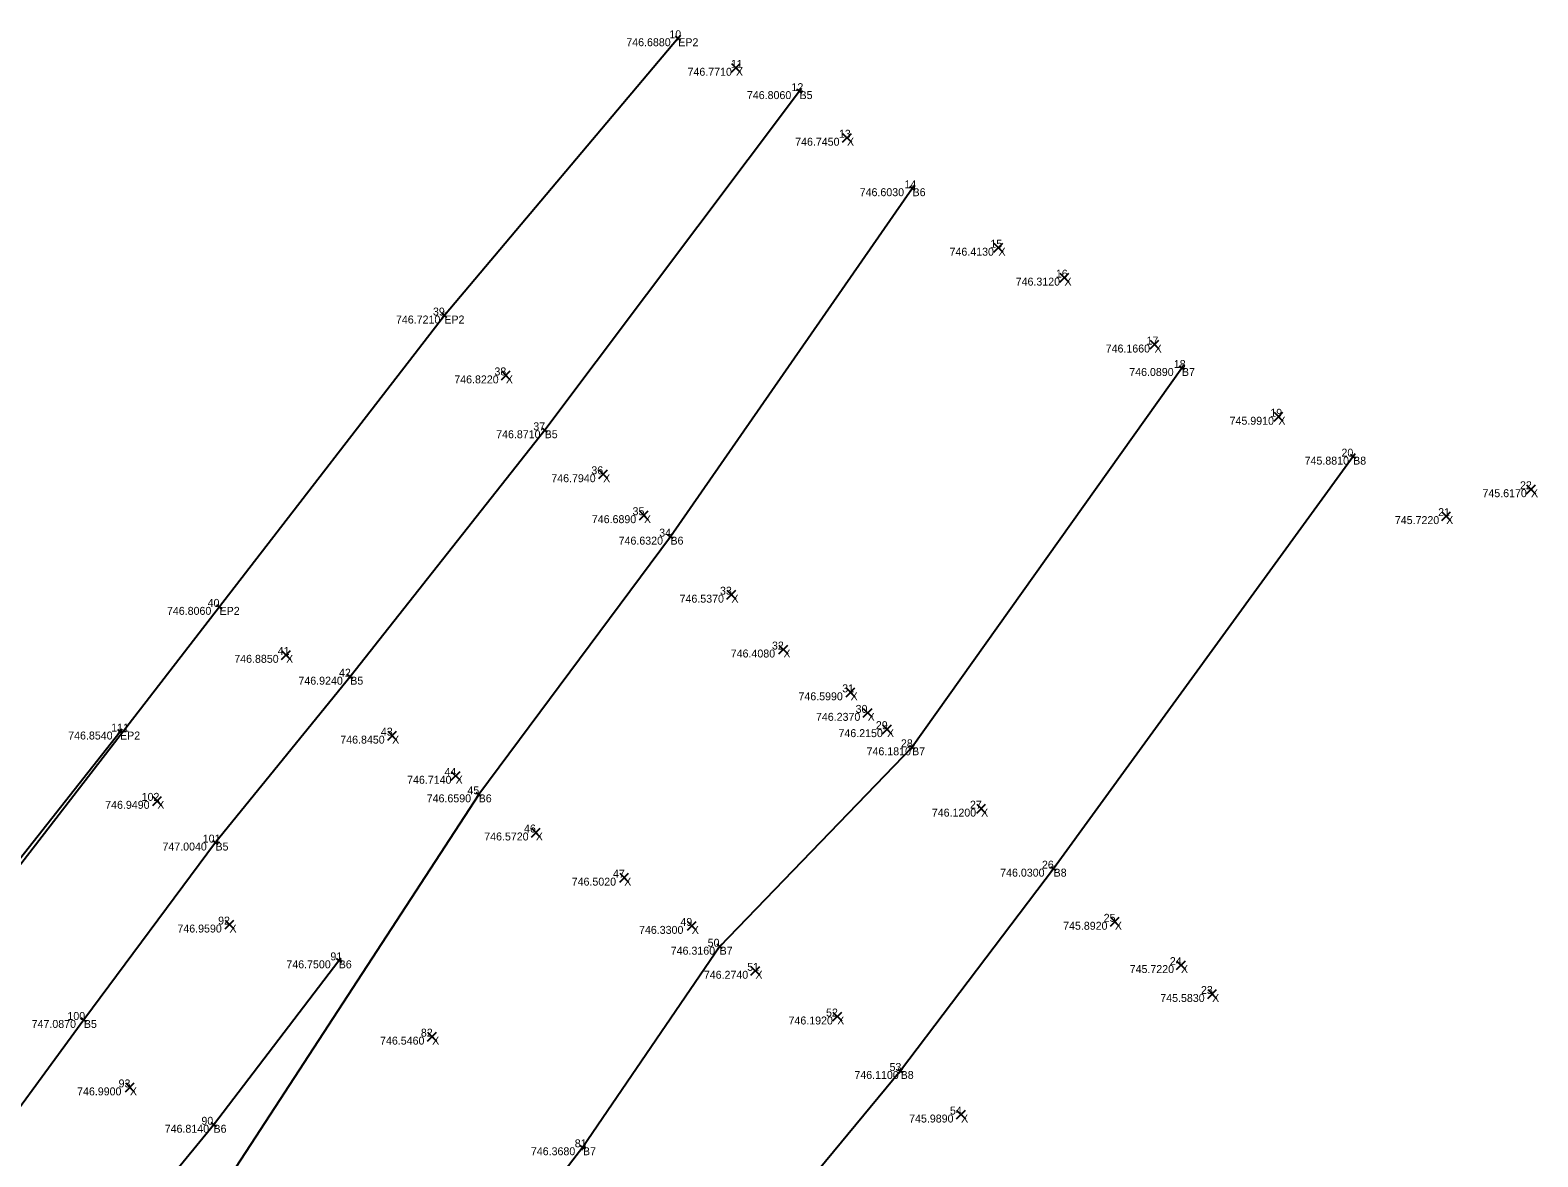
# Model space of a CAD drawing. Extents: x 1857337 to 1857837, y 693958 to 694371.
# Drawn here: x 1857723.4 to 1857837.1, y 694231.5 to 694316.5 of the extents above; entities that cross this region are included whole.
import ezdxf

# ---------------------------------------------------------------- set-up
doc = ezdxf.new("R2010")
doc.units = 0
for name, color, linetype in [('BR_X_SV_Pier_Cap_Bottom', 7, 'Continuous'), ('SV_X_Random_Point', 7, 'Continuous'), ('SV_X_Text_Comment', 7, 'Continuous'), ('SV_X_Text_Description', 7, 'Continuous'), ('SV_X_Text_Elevation', 7, 'Continuous'), ('SV_X_Text_Name', 7, 'Continuous'), ('UT_X_Electric_Cells', 7, 'Continuous')]:
    doc.layers.add(name, color=color, linetype=linetype)

msp = doc.modelspace()

# ---------------------------------------------------------------- linework, layer by layer
at = {"layer": 'BR_X_SV_Pier_Cap_Bottom'}
for p, q in [((1857772.47, 694315.76), (1857772.08, 694316.09)), ((1857772.44, 694316.12), (1857772.11, 694315.73)), ((1857772.28, 694315.92), (1857772.28, 694315.92)), ((1857781.63, 694311.78), (1857781.23, 694312.08)), ((1857781.58, 694312.13), (1857781.28, 694311.73)), ((1857781.43, 694311.93), (1857781.43, 694311.93)), ((1857790.16, 694304.46), (1857789.75, 694304.74)), ((1857790.1, 694304.8), (1857789.81, 694304.39)), ((1857789.96, 694304.6), (1857789.96, 694304.6)), ((1857754.82, 694294.83), (1857754.44, 694295.16)), ((1857754.79, 694295.19), (1857754.47, 694294.8)), ((1857754.63, 694294.99), (1857754.63, 694294.99)), ((1857810.48, 694290.89), (1857810.08, 694291.18)), ((1857810.42, 694291.24), (1857810.14, 694290.83)), ((1857810.28, 694291.03), (1857810.28, 694291.03)), ((1857762.4, 694286.18), (1857762, 694286.48)), ((1857762.35, 694286.53), (1857762.05, 694286.13)), ((1857762.2, 694286.33), (1857762.2, 694286.33)), ((1857823.41, 694284.2), (1857823, 694284.49)), ((1857823.35, 694284.55), (1857823.06, 694284.14)), ((1857823.2, 694284.34), (1857823.2, 694284.34)), ((1857771.9, 694278.15), (1857771.49, 694278.44)), ((1857771.83, 694278.5), (1857771.55, 694278.09)), ((1857771.69, 694278.3), (1857771.69, 694278.3)), ((1857737.87, 694272.84), (1857737.47, 694273.15)), ((1857737.82, 694273.2), (1857737.52, 694272.8)), ((1857737.67, 694273), (1857737.67, 694273)), ((1857747.73, 694267.58), (1857747.33, 694267.89)), ((1857747.68, 694267.93), (1857747.38, 694267.54)), ((1857747.53, 694267.73), (1857747.53, 694267.73)), ((1857729.96, 694263.75), (1857730.35, 694263.44)), ((1857730, 694263.4), (1857730.31, 694263.79)), ((1857730.16, 694263.59), (1857730.16, 694263.59)), ((1857790.13, 694262.25), (1857789.72, 694262.54)), ((1857790.07, 694262.6), (1857789.78, 694262.19)), ((1857789.92, 694262.4), (1857789.92, 694262.4)), ((1857757.42, 694258.7), (1857757.02, 694259)), ((1857757.37, 694259.05), (1857757.07, 694258.65)), ((1857757.22, 694258.85), (1857757.22, 694258.85)), ((1857737.56, 694255.06), (1857737.17, 694255.37)), ((1857737.52, 694255.41), (1857737.2, 694255.02)), ((1857737.36, 694255.21), (1857737.36, 694255.21)), ((1857800.8, 694253.1), (1857800.39, 694253.39)), ((1857800.74, 694253.45), (1857800.45, 694253.04)), ((1857800.6, 694253.24), (1857800.6, 694253.24)), ((1857746.46, 694246.47), (1857746.86, 694246.17)), ((1857746.51, 694246.12), (1857746.81, 694246.52)), ((1857775.58, 694247.18), (1857775.22, 694247.53)), ((1857775.57, 694247.53), (1857775.22, 694247.17)), ((1857775.4, 694247.35), (1857775.4, 694247.35)), ((1857746.66, 694246.32), (1857746.66, 694246.32)), ((1857727.63, 694241.67), (1857727.23, 694241.97)), ((1857727.58, 694242.02), (1857727.28, 694241.62)), ((1857727.43, 694241.82), (1857727.43, 694241.82)), ((1857789.26, 694237.81), (1857788.86, 694238.12)), ((1857789.21, 694238.16), (1857788.91, 694237.77)), ((1857789.06, 694237.97), (1857789.06, 694237.97)), ((1857737.01, 694234.07), (1857737.4, 694233.76)), ((1857737.05, 694233.72), (1857737.37, 694234.11)), ((1857737.21, 694233.91), (1857737.21, 694233.91)), ((1857765.29, 694232.07), (1857764.88, 694232.35)), ((1857765.23, 694232.42), (1857764.95, 694232)), ((1857765.09, 694232.21), (1857765.09, 694232.21))]:
    msp.add_line(p, q, dxfattribs=at)
at = {"layer": 'SV_X_Random_Point'}
msp.add_lwpolyline([(1857772.28, 694315.92), (1857754.63, 694294.99), (1857737.67, 694273), (1857683.54, 694202.91), (1857696.08, 694219.12), (1857709.71, 694237.31), (1857720.48, 694251.33), (1857730.16, 694263.59)], dxfattribs=at)
at = {"layer": 'SV_X_Text_Elevation'}
for p, q in [((1857776.3, 694313.35), (1857776.96, 694314.02)), ((1857776.3, 694314.02), (1857776.96, 694313.35)), ((1857784.67, 694308.07), (1857785.34, 694308.74)), ((1857784.67, 694308.74), (1857785.34, 694308.07)), ((1857796.1, 694299.78), (1857796.77, 694300.45)), ((1857796.1, 694300.45), (1857796.77, 694299.78)), ((1857801.08, 694297.52), (1857801.75, 694298.18)), ((1857801.08, 694298.18), (1857801.75, 694297.52)), ((1857807.88, 694292.47), (1857808.55, 694293.14)), ((1857807.88, 694293.14), (1857808.55, 694292.47)), ((1857758.94, 694290.14), (1857759.6, 694290.81)), ((1857758.94, 694290.81), (1857759.6, 694290.14)), ((1857817.23, 694287.02), (1857817.9, 694287.69)), ((1857817.23, 694287.69), (1857817.9, 694287.02)), ((1857766.28, 694282.68), (1857766.94, 694283.34)), ((1857766.28, 694283.34), (1857766.94, 694282.68)), ((1857836.29, 694281.54), (1857836.95, 694282.21)), ((1857836.29, 694282.21), (1857836.95, 694281.54)), ((1857769.36, 694279.58), (1857770.02, 694280.25)), ((1857769.36, 694280.25), (1857770.02, 694279.58)), ((1857829.89, 694279.51), (1857830.55, 694280.18)), ((1857829.89, 694280.18), (1857830.55, 694279.51)), ((1857775.95, 694273.59), (1857776.62, 694274.25)), ((1857775.95, 694274.25), (1857776.62, 694273.59)), ((1857742.35, 694269.04), (1857743.02, 694269.71)), ((1857742.35, 694269.71), (1857743.02, 694269.04)), ((1857779.87, 694269.45), (1857780.54, 694270.12)), ((1857779.87, 694270.12), (1857780.54, 694269.45)), ((1857784.95, 694266.22), (1857785.61, 694266.88)), ((1857784.95, 694266.88), (1857785.61, 694266.22)), ((1857786.24, 694264.67), (1857786.9, 694265.34)), ((1857786.24, 694265.34), (1857786.9, 694264.67)), ((1857750.36, 694262.95), (1857751.02, 694263.61)), ((1857750.36, 694263.61), (1857751.02, 694262.95)), ((1857787.7, 694263.43), (1857788.36, 694264.1)), ((1857787.7, 694264.1), (1857788.36, 694263.43)), ((1857755.15, 694259.91), (1857755.82, 694260.58)), ((1857755.15, 694260.58), (1857755.82, 694259.91)), ((1857732.64, 694258.02), (1857733.3, 694258.69)), ((1857732.64, 694258.69), (1857733.3, 694258.02)), ((1857794.8, 694257.44), (1857795.46, 694258.11)), ((1857794.8, 694258.11), (1857795.46, 694257.44)), ((1857761.2, 694255.63), (1857761.86, 694256.3)), ((1857761.2, 694256.3), (1857761.86, 694255.63)), ((1857767.86, 694252.22), (1857768.53, 694252.89)), ((1857767.86, 694252.89), (1857768.53, 694252.22)), ((1857738.08, 694248.69), (1857738.75, 694249.36)), ((1857738.08, 694249.36), (1857738.75, 694248.69)), ((1857772.97, 694248.59), (1857773.63, 694249.26)), ((1857772.97, 694249.26), (1857773.63, 694248.59)), ((1857804.89, 694248.9), (1857805.55, 694249.57)), ((1857804.89, 694249.57), (1857805.55, 694248.9)), ((1857777.76, 694245.2), (1857778.43, 694245.86)), ((1857777.76, 694245.86), (1857778.43, 694245.2)), ((1857809.87, 694245.63), (1857810.54, 694246.29)), ((1857809.87, 694246.29), (1857810.54, 694245.63)), ((1857812.23, 694243.44), (1857812.89, 694244.11)), ((1857812.23, 694244.11), (1857812.89, 694243.44)), ((1857783.94, 694241.75), (1857784.61, 694242.42)), ((1857783.94, 694242.42), (1857784.61, 694241.75)), ((1857753.37, 694240.23), (1857754.04, 694240.9)), ((1857753.37, 694240.9), (1857754.04, 694240.23)), ((1857730.57, 694236.4), (1857731.23, 694237.07)), ((1857730.57, 694237.07), (1857731.23, 694236.4)), ((1857793.28, 694234.35), (1857793.95, 694235.02)), ((1857793.28, 694235.02), (1857793.95, 694234.35))]:
    msp.add_line(p, q, dxfattribs=at)
at = {"layer": 'UT_X_Electric_Cells'}
for points in [[(1857781.43, 694311.93), (1857762.2, 694286.33), (1857747.53, 694267.73), (1857737.36, 694255.21), (1857727.43, 694241.82), (1857719.13, 694230.5), (1857704.83, 694212.34), (1857686.36, 694188.29)], [(1857789.96, 694304.6), (1857771.69, 694278.3), (1857757.22, 694258.85), (1857703.3, 694176.12), (1857697.07, 694181.68), (1857715.68, 694205.65), (1857728.74, 694223.57), (1857737.21, 694233.91), (1857746.66, 694246.32)], [(1857810.28, 694291.03), (1857789.92, 694262.4), (1857775.4, 694247.35), (1857765.09, 694232.21), (1857755.64, 694219.95), (1857747.98, 694210.11), (1857734.18, 694191.79), (1857715.87, 694167.45)], [(1857823.2, 694284.34), (1857800.6, 694253.24), (1857789.06, 694237.97), (1857776.66, 694222.99), (1857768.19, 694210.93), (1857761.12, 694200.8), (1857747.1, 694182.05), (1857731.26, 694157.25)]]:
    msp.add_lwpolyline(points, dxfattribs=at)

# ---------------------------------------------------------------- texts
at = {"layer": 'SV_X_Text_Comment'}
for s, p in [('EP2', (1857772.28, 694315.32)), ('X', (1857776.63, 694313.09)), ('B5', (1857781.43, 694311.33)), ('X', (1857785.01, 694307.81)), ('B6', (1857789.96, 694304)), ('X', (1857796.44, 694299.51)), ('X', (1857801.42, 694297.25)), ('EP2', (1857754.63, 694294.39)), ('X', (1857808.22, 694292.2)), ('B7', (1857810.28, 694290.43)), ('X', (1857759.27, 694289.87)), ('B5', (1857762.2, 694285.73)), ('X', (1857817.56, 694286.75)), ('B8', (1857823.2, 694283.74)), ('X', (1857766.61, 694282.41)), ('X', (1857836.62, 694281.28)), ('X', (1857769.69, 694279.32)), ('X', (1857830.22, 694279.25)), ('B6', (1857771.69, 694277.7)), ('X', (1857776.29, 694273.32)), ('EP2', (1857737.67, 694272.4)), ('X', (1857742.69, 694268.78)), ('X', (1857780.21, 694269.18)), ('B5', (1857747.53, 694267.13)), ('X', (1857785.28, 694265.95)), ('X', (1857786.57, 694264.4)), ('EP2', (1857730.16, 694262.99)), ('X', (1857788.03, 694263.17)), ('X', (1857750.69, 694262.68)), ('B7', (1857789.92, 694261.8)), ('X', (1857755.48, 694259.65)), ('X', (1857732.97, 694257.76)), ('B6', (1857757.22, 694258.25)), ('X', (1857795.13, 694257.17)), ('X', (1857761.53, 694255.37)), ('B5', (1857737.36, 694254.61)), ('X', (1857768.2, 694251.96)), ('B8', (1857800.6, 694252.64)), ('X', (1857738.42, 694248.42)), ('X', (1857773.3, 694248.32)), ('X', (1857805.22, 694248.63)), ('B7', (1857775.4, 694246.75)), ('B6', (1857746.66, 694245.72)), ('X', (1857778.1, 694244.93)), ('X', (1857810.21, 694245.36)), ('X', (1857812.56, 694243.18)), ('X', (1857784.27, 694241.48)), ('B5', (1857727.43, 694241.22)), ('X', (1857753.71, 694239.96)), ('B8', (1857789.06, 694237.37)), ('X', (1857730.9, 694236.13)), ('B6', (1857737.21, 694233.31)), ('X', (1857793.62, 694234.08)), ('B7', (1857765.09, 694231.61))]:
    msp.add_text(s, height=0.6, dxfattribs=at).set_placement(p)
at = {"layer": 'SV_X_Text_Description'}
for s, p in [('746.6880', (1857768.36, 694315.32)), ('746.7710', (1857772.98, 694313.09)), ('746.8060', (1857777.46, 694311.33)), ('746.7450', (1857781.1, 694307.81)), ('746.6030', (1857785.97, 694304)), ('746.4130', (1857792.75, 694299.51)), ('746.3120', (1857797.74, 694297.25)), ('746.7210', (1857750.98, 694294.39)), ('746.1660', (1857804.53, 694292.2)), ('746.0890', (1857806.31, 694290.43)), ('746.8220', (1857755.38, 694289.87)), ('746.8710', (1857758.54, 694285.73)), ('745.9910', (1857813.88, 694286.75)), ('745.8810', (1857819.54, 694283.74)), ('746.7940', (1857762.7, 694282.41)), ('745.6170', (1857832.96, 694281.28)), ('746.6890', (1857765.76, 694279.32)), ('745.7220', (1857826.35, 694279.25)), ('746.6320', (1857767.78, 694277.7)), ('746.5370', (1857772.38, 694273.32)), ('746.8060', (1857733.7, 694272.4)), ('746.8850', (1857738.78, 694268.78)), ('746.4080', (1857776.24, 694269.18)), ('746.9240', (1857743.62, 694267.13)), ('746.5990', (1857781.35, 694265.95)), ('746.2370', (1857782.67, 694264.4)), ('746.8540', (1857726.25, 694262.99)), ('746.2150', (1857784.37, 694263.17)), ('746.8450', (1857746.78, 694262.68)), ('746.1810', (1857786.49, 694261.8)), ('746.7140', (1857751.82, 694259.65)), ('746.9490', (1857729.04, 694257.76)), ('746.6590', (1857753.3, 694258.25)), ('746.1200', (1857791.41, 694257.17)), ('746.5720', (1857757.64, 694255.37)), ('747.0040', (1857733.36, 694254.61)), ('746.5020', (1857764.24, 694251.96)), ('746.0300', (1857796.57, 694252.64)), ('746.9590', (1857734.49, 694248.42)), ('746.3300', (1857769.32, 694248.32)), ('745.8920', (1857801.32, 694248.63)), ('746.3160', (1857771.71, 694246.75)), ('746.7500', (1857742.71, 694245.72)), ('746.2740', (1857774.21, 694244.93)), ('745.7220', (1857806.34, 694245.36)), ('745.5830', (1857808.65, 694243.18)), ('746.1920', (1857780.6, 694241.48)), ('747.0870', (1857723.49, 694241.22)), ('746.5460', (1857749.78, 694239.96)), ('746.1100', (1857785.57, 694237.37)), ('746.9900', (1857726.92, 694236.13)), ('746.8140', (1857733.53, 694233.31)), ('745.9890', (1857789.7, 694234.08)), ('746.3680', (1857761.16, 694231.61))]:
    msp.add_text(s, height=0.6, dxfattribs=at).set_placement(p)
at = {"layer": 'SV_X_Text_Name'}
for s, p in [('10', (1857771.61, 694315.92)), ('11', (1857776.25, 694313.69)), ('12', (1857780.82, 694311.93)), ('13', (1857784.4, 694308.41)), ('14', (1857789.35, 694304.6)), ('15', (1857795.83, 694300.11)), ('16', (1857800.77, 694297.85)), ('39', (1857753.77, 694294.99)), ('17', (1857807.61, 694292.8)), ('38', (1857758.41, 694290.47)), ('18', (1857809.67, 694291.03)), ('19', (1857816.95, 694287.35)), ('37', (1857761.34, 694286.33)), ('20', (1857822.32, 694284.34)), ('36', (1857765.72, 694283.01)), ('22', (1857835.79, 694281.88)), ('35', (1857768.83, 694279.92)), ('21', (1857829.61, 694279.85)), ('34', (1857770.84, 694278.3)), ('33', (1857775.43, 694273.92)), ('40', (1857736.77, 694273)), ('32', (1857779.35, 694269.78)), ('41', (1857742.06, 694269.38)), ('42', (1857746.68, 694267.73)), ('31', (1857784.65, 694266.55)), ('30', (1857785.66, 694265)), ('111', (1857729.49, 694263.59)), ('43', (1857749.84, 694263.28)), ('29', (1857787.19, 694263.77)), ('28', (1857789.08, 694262.4)), ('44', (1857754.64, 694260.25)), ('102', (1857731.79, 694258.36)), ('45', (1857756.37, 694258.85)), ('27', (1857794.29, 694257.77)), ('101', (1857736.4, 694255.21)), ('46', (1857760.64, 694255.97)), ('26', (1857799.72, 694253.24)), ('47', (1857767.35, 694252.56)), ('92', (1857737.56, 694249.02)), ('49', (1857772.44, 694248.92)), ('25', (1857804.38, 694249.23)), ('50', (1857774.5, 694247.35)), ('91', (1857746.03, 694246.32)), ('24', (1857809.37, 694245.96)), ('51', (1857777.48, 694245.53)), ('23', (1857811.72, 694243.78)), ('100', (1857726.19, 694241.82)), ('52', (1857783.43, 694242.08)), ('82', (1857752.86, 694240.56)), ('53', (1857788.22, 694237.97)), ('93', (1857730.05, 694236.73)), ('54', (1857792.78, 694234.68)), ('90', (1857736.3, 694233.91)), ('81', (1857764.47, 694232.21))]:
    msp.add_text(s, height=0.6, dxfattribs=at).set_placement(p)

doc.saveas('drawing.dxf')
